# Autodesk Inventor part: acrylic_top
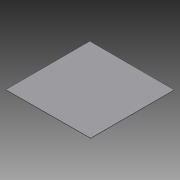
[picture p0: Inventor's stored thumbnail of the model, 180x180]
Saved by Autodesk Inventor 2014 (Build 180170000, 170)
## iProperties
Created: 2014-06
Part Number: acrylic_top
Material: Generic
Document SubType Name: Modeling
Designer: t_emanb
Density: 1 g/cm^3
Appearance: Default
Author: t_emanb
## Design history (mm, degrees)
sketch "Sketch1"
  geometry: L1 (0, 0)-(-612.775, 0); L2 (-612.775, 0)-(-612.775, 606.425); L3 (-612.775, 606.425)-(0, 609.6); L4 (0, 609.6)-(0, 0)
  constraints: 8 end point, 1 horizontal, 1 parallel, 1 perpendicular
  dimensions: "d1" = 609.6 distance of L3.end L1.start; "d2" = 606.425 distance of L1.end L2.end; "d4" = 612.775 horizontal distance of L2.end L3.end; "d5" = 612.775 distance of L1.start L1.end (derived)
extrude "Extrusion1" new body sketch "Sketch1" distance "d6" = 3.048; taper "d7" = 0 deg
body "Solid1"
